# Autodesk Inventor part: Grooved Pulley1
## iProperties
Created: 2011-05
Part Number: Grooved Pulley1
Material: Steel
Document SubType Name: Modeling
Designer: 904Chiaki
Density: 1 g/cm^3
CustomPartVersion: 1
Author: 904Chiaki
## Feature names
1. Body [Revolution]
2. Groove [Revolution]
3. Fillet External
4. Fillet Internal
5. Groove Pattern [Rectangular Pattern]
6. Extrusion1
7. Extrusion2
8. Mirror1
9. Chamfer1
10. Chamfer2
11. Extrusion3
